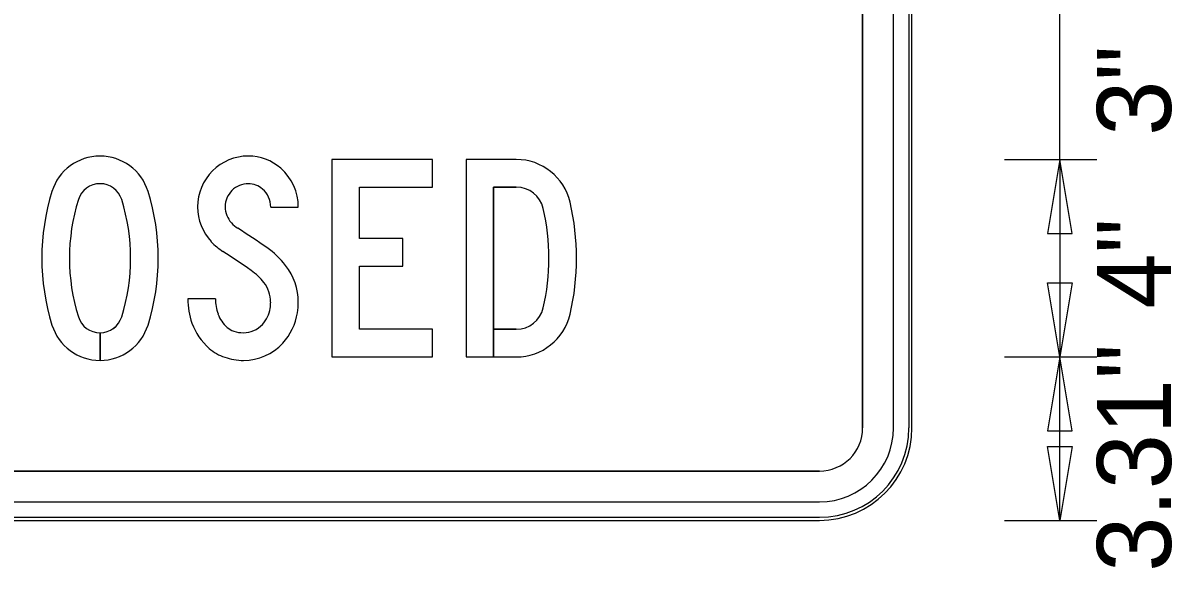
# Model space of a CAD drawing. Extents: x 1788.1 to 1851.2, y 237.2 to 283.4.
# Drawn here: x 1840.936 to 1843.265, y 275.952 to 277.056 of the extents above; entities that cross this region are included whole.
import ezdxf

# ---------------------------------------------------------------- set-up
doc = ezdxf.new("R2010")
doc.units = 0
for name, color, linetype in [('GSBWFILL', 7, 'Continuous'), ('GSCOLORFILL', 7, 'Continuous'), ('GSDIMS', 7, 'Continuous'), ('GSOUTLINE', 7, 'Continuous')]:
    doc.layers.add(name, color=color, linetype=linetype)

msp = doc.modelspace()

# ---------------------------------------------------------------- linework, layer by layer
at = {"layer": 'GSBWFILL'}
for p, q in [((1842.6379, 277.6605), (1842.6379, 276.2355)), ((1842.7004, 276.2355), (1842.7004, 277.6605)), ((1842.7379, 276.2355), (1842.7379, 277.6605)), ((1841.0919, 276.4282), (1841.0919, 276.3722)), ((1841.0919, 276.3722), (1841.0919, 276.4282)), ((1841.9358, 276.4352), (1841.8899, 276.4352)), ((1842.5504, 276.148), (1839.926, 276.148)), ((1839.926, 276.0855), (1842.5504, 276.0855)), ((1839.9254, 276.048), (1842.5504, 276.048))]:
    msp.add_line(p, q, dxfattribs=at)
msp.add_lwpolyline([(1841.6179, 276.4352), (1841.6179, 276.5632), (1841.7055, 276.5632), (1841.7055, 276.6192), (1841.6179, 276.6192), (1841.6179, 276.7232), (1841.7659, 276.7232), (1841.7659, 276.7792), (1841.5619, 276.7792), (1841.5619, 276.3792), (1841.7659, 276.3792), (1841.7659, 276.4352)], close=True, dxfattribs=at)
for points in [[(1841.9358, 276.7792), (1841.8339, 276.7792), (1841.8339, 276.3792), (1841.8899, 276.3792), (1841.8899, 276.7232), (1841.9358, 276.7232)], [(1841.4379, 276.6829), (1841.4939, 276.6829)], [(1841.3259, 276.4969), (1841.2699, 276.4969)], [(1841.8899, 276.4352), (1841.8899, 276.3792), (1841.9358, 276.3792)]]:
    msp.add_lwpolyline(points, dxfattribs=at)
for centre, radius, start, end in [((1841.0919, 276.6842), 0.102, 17.3283, 162.6717), ((1841.9358, 276.6672), 0.112, 13.109, 90), ((1841.0919, 276.6842), 0.046, 17.3283, 162.6717), ((1841.9358, 276.6672), 0.056, 13.109, 90), ((1841.4284, 276.5792), 0.4545, 162.6717, 197.3283), ((1841.4284, 276.5792), 0.3985, 162.6717, 197.3283), ((1840.7554, 276.5792), 0.3985, 342.6717, 17.3283), ((1840.7554, 276.5792), 0.4545, 342.6717, 17.3283), ((1841.5579, 276.5792), 0.444, 346.891, 13.109), ((1841.5579, 276.5792), 0.5, 346.891, 13.109), ((1841.9358, 276.4912), 0.056, 270, 346.891), ((1841.9358, 276.4912), 0.112, 270, 346.891), ((1841.0919, 276.4742), 0.102, 197.3283, 270), ((1841.0919, 276.4742), 0.046, 197.3283, 270), ((1841.0919, 276.4742), 0.046, 270.0249, 342.6717), ((1841.0919, 276.4742), 0.102, 270.0112, 342.6717), ((1842.5504, 276.2355), 0.15, 270, 0), ((1842.5504, 276.2355), 0.0875, 270, 0), ((1842.5504, 276.2355), 0.1875, 270, 0)]:
    msp.add_arc(centre, radius, start, end, dxfattribs=at)
for centre, major_axis, start_param, end_param in [((1841.3926, 276.6832), (0, 0.103), 6.283184, 7.853982), ((1841.3926, 276.6867), (0, 0.0995), 5.561989, 6.283185), ((1841.3893, 276.6829), (0, 0.1046), 4.712389, 5.561989), ((1841.3926, 276.6832), (0, 0.047), 6.283183, 7.853981), ((1841.3926, 276.6867), (0, 0.0435), 5.561989, 6.283185), ((1841.3893, 276.6829), (0, 0.0486), 4.712389, 5.561989), ((1841.3928, 276.6832), (0, 0.1032), 1.570796, 2.321595), ((1841.3928, 276.6832), (0, 0.0472), 1.570796, 2.321595), ((1841.4099, 276.699), (0, 0.0705), 2.321595, 2.56746), ((1840.093, 274.6631), (0, 2.3542), 5.679143, 5.709053), ((1841.4099, 276.699), (0, 0.1265), 2.321595, 2.56746), ((1840.093, 274.6631), (0, 2.2982), 5.679143, 5.709053), ((1841.3323, 276.4589), (0, 0.1722), 5.373599, 5.679143), ((1841.3323, 276.4589), (0, 0.1162), 5.373599, 5.679143), ((1841.372, 276.4899), (0, 0.1218), 4.712389, 5.373599), ((1841.372, 276.4899), (0, 0.0658), 4.712389, 5.373599), ((1841.4174, 276.4969), (0, 0.1475), 1.570808, 1.909921), ((1841.4174, 276.4969), (0, 0.0915), 1.570816, 1.909918), ((1841.3607, 276.4899), (0, 0.0772), 4.552917, 4.712389), ((1841.3607, 276.4899), (0, 0.1332), 4.552917, 4.712389), ((1841.3921, 276.488), (0, 0.0647), 1.909925, 2.431476), ((1841.3749, 276.4876), (0, 0.0628), 3.967076, 4.552917), ((1841.3749, 276.4876), (0, 0.1188), 3.967076, 4.552917), ((1841.3921, 276.488), (0, 0.1207), 1.909925, 2.431476), ((1841.3757, 276.4689), (0, 0.0396), 2.431476, 2.811358), ((1841.3827, 276.4804), (0, 0.0522), 3.141593, 3.967076), ((1841.3827, 276.4892), (0, 0.061), 2.811358, 3.141593), ((1841.3757, 276.4689), (0, 0.0956), 2.431476, 2.811358), ((1841.3827, 276.4804), (0, 0.1082), 3.141593, 3.967076), ((1841.3827, 276.4892), (0, 0.117), 2.811358, 3.141593)]:
    msp.add_ellipse(centre, major_axis=major_axis, ratio=0.999991, start_param=start_param, end_param=end_param, dxfattribs=at)
at = {"layer": 'GSCOLORFILL'}
for p, q in [((1842.6379, 277.6605), (1842.6379, 276.2355)), ((1842.7004, 276.2355), (1842.7004, 277.6605)), ((1842.7316, 277.6605), (1842.7316, 276.2355)), ((1842.7379, 276.2355), (1842.7379, 277.6605)), ((1842.7379, 276.2355), (1842.7379, 277.6605)), ((1841.0919, 276.4282), (1841.0919, 276.3722)), ((1841.0919, 276.3722), (1841.0919, 276.4282)), ((1841.9358, 276.4352), (1841.8899, 276.4352)), ((1842.5504, 276.148), (1839.926, 276.148)), ((1839.926, 276.0855), (1842.5504, 276.0855)), ((1839.9254, 276.048), (1842.5504, 276.048)), ((1842.5504, 276.0542), (1839.9255, 276.0542)), ((1839.9255, 276.048), (1842.5504, 276.048))]:
    msp.add_line(p, q, dxfattribs=at)
msp.add_lwpolyline([(1841.6179, 276.4352), (1841.6179, 276.5632), (1841.7055, 276.5632), (1841.7055, 276.6192), (1841.6179, 276.6192), (1841.6179, 276.7232), (1841.7659, 276.7232), (1841.7659, 276.7792), (1841.5619, 276.7792), (1841.5619, 276.3792), (1841.7659, 276.3792), (1841.7659, 276.4352)], close=True, dxfattribs=at)
for points in [[(1841.9358, 276.7792), (1841.8339, 276.7792), (1841.8339, 276.3792), (1841.8899, 276.3792), (1841.8899, 276.7232), (1841.9358, 276.7232)], [(1841.4379, 276.6829), (1841.4939, 276.6829)], [(1841.3259, 276.4969), (1841.2699, 276.4969)], [(1841.8899, 276.4352), (1841.8899, 276.3792), (1841.9358, 276.3792)]]:
    msp.add_lwpolyline(points, dxfattribs=at)
for centre, radius, start, end in [((1841.0919, 276.6842), 0.102, 17.3283, 162.6717), ((1841.9358, 276.6672), 0.112, 13.109, 90), ((1841.0919, 276.6842), 0.046, 17.3283, 162.6717), ((1841.9358, 276.6672), 0.056, 13.109, 90), ((1841.4284, 276.5792), 0.4545, 162.6717, 197.3283), ((1841.4284, 276.5792), 0.3985, 162.6717, 197.3283), ((1840.7554, 276.5792), 0.3985, 342.6717, 17.3283), ((1840.7554, 276.5792), 0.4545, 342.6717, 17.3283), ((1841.5579, 276.5792), 0.444, 346.891, 13.109), ((1841.5579, 276.5792), 0.5, 346.891, 13.109), ((1841.9358, 276.4912), 0.056, 270, 346.891), ((1841.9358, 276.4912), 0.112, 270, 346.891), ((1841.0919, 276.4742), 0.102, 197.3283, 270), ((1841.0919, 276.4742), 0.046, 197.3283, 270), ((1841.0919, 276.4742), 0.046, 270.0249, 342.6717), ((1841.0919, 276.4742), 0.102, 270.0112, 342.6717), ((1842.5504, 276.2355), 0.1875, 270, 0), ((1842.5504, 276.2355), 0.15, 270, 0), ((1842.5504, 276.2355), 0.0875, 270, 0), ((1842.5504, 276.2355), 0.1875, 270, 0), ((1842.5504, 276.2355), 0.1812, 270, 0)]:
    msp.add_arc(centre, radius, start, end, dxfattribs=at)
for centre, major_axis, start_param, end_param in [((1841.3926, 276.6832), (0, 0.103), 6.283184, 7.853982), ((1841.3926, 276.6867), (0, 0.0995), 5.561989, 6.283185), ((1841.3893, 276.6829), (0, 0.1046), 4.712389, 5.561989), ((1841.3926, 276.6832), (0, 0.047), 6.283183, 7.853981), ((1841.3926, 276.6867), (0, 0.0435), 5.561989, 6.283185), ((1841.3893, 276.6829), (0, 0.0486), 4.712389, 5.561989), ((1841.3928, 276.6832), (0, 0.1032), 1.570796, 2.321595), ((1841.3928, 276.6832), (0, 0.0472), 1.570796, 2.321595), ((1841.4099, 276.699), (0, 0.0705), 2.321595, 2.56746), ((1840.093, 274.6631), (0, 2.3542), 5.679143, 5.709053), ((1841.4099, 276.699), (0, 0.1265), 2.321595, 2.56746), ((1840.093, 274.6631), (0, 2.2982), 5.679143, 5.709053), ((1841.3323, 276.4589), (0, 0.1722), 5.373599, 5.679143), ((1841.3323, 276.4589), (0, 0.1162), 5.373599, 5.679143), ((1841.372, 276.4899), (0, 0.1218), 4.712389, 5.373599), ((1841.372, 276.4899), (0, 0.0658), 4.712389, 5.373599), ((1841.4174, 276.4969), (0, 0.1475), 1.570808, 1.909921), ((1841.4174, 276.4969), (0, 0.0915), 1.570816, 1.909918), ((1841.3607, 276.4899), (0, 0.0772), 4.552917, 4.712389), ((1841.3607, 276.4899), (0, 0.1332), 4.552917, 4.712389), ((1841.3921, 276.488), (0, 0.0647), 1.909925, 2.431476), ((1841.3749, 276.4876), (0, 0.0628), 3.967076, 4.552917), ((1841.3749, 276.4876), (0, 0.1188), 3.967076, 4.552917), ((1841.3921, 276.488), (0, 0.1207), 1.909925, 2.431476), ((1841.3757, 276.4689), (0, 0.0396), 2.431476, 2.811358), ((1841.3827, 276.4804), (0, 0.0522), 3.141593, 3.967076), ((1841.3827, 276.4892), (0, 0.061), 2.811358, 3.141593), ((1841.3757, 276.4689), (0, 0.0956), 2.431476, 2.811358), ((1841.3827, 276.4804), (0, 0.1082), 3.141593, 3.967076), ((1841.3827, 276.4892), (0, 0.117), 2.811358, 3.141593)]:
    msp.add_ellipse(centre, major_axis=major_axis, ratio=0.999991, start_param=start_param, end_param=end_param, dxfattribs=at)
at = {"layer": 'GSDIMS'}
for p, q in [((1843.0379, 276.7792), (1843.0379, 277.0792)), ((1842.9254, 276.7792), (1843.1129, 276.7792)), ((1842.9254, 276.7792), (1843.1129, 276.7792)), ((1843.0379, 276.7792), (1843.0379, 276.3792)), ((1842.9254, 276.3792), (1843.1129, 276.3792)), ((1842.9254, 276.3792), (1843.1129, 276.3792)), ((1843.0379, 276.048), (1843.0379, 276.3792)), ((1842.9254, 276.048), (1843.1129, 276.048)), ((1842.9254, 276.048), (1842.9254, 276.048))]:
    msp.add_line(p, q, dxfattribs=at)
for points in [[(1843.0379, 276.7792), (1843.0129, 276.6292), (1843.0629, 276.6292)], [(1843.0379, 276.3792), (1843.0129, 276.5292), (1843.0629, 276.5292)], [(1843.0379, 276.3792), (1843.0129, 276.2292), (1843.0629, 276.2292)], [(1843.0379, 276.048), (1843.0129, 276.198), (1843.0629, 276.198)]]:
    msp.add_lwpolyline(points, close=True, dxfattribs=at)
at = {"layer": 'GSOUTLINE'}
for p, q in [((1842.6379, 276.2355), (1842.6379, 277.6605)), ((1842.7004, 276.2355), (1842.7004, 277.6605)), ((1842.7379, 276.2355), (1842.7379, 277.6605)), ((1841.8899, 276.4352), (1841.9358, 276.4352)), ((1841.9358, 276.3792), (1841.9358, 276.3792)), ((1839.9254, 276.148), (1842.5504, 276.148)), ((1839.9254, 276.0855), (1842.5504, 276.0855)), ((1839.9254, 276.048), (1842.5504, 276.048))]:
    msp.add_line(p, q, dxfattribs=at)
msp.add_lwpolyline([(1841.6179, 276.4352), (1841.6179, 276.5632), (1841.7055, 276.5632), (1841.7055, 276.6192), (1841.6179, 276.6192), (1841.6179, 276.7232), (1841.7659, 276.7232), (1841.7659, 276.7792), (1841.5619, 276.7792), (1841.5619, 276.3792), (1841.7659, 276.3792), (1841.7659, 276.4352)], close=True, dxfattribs=at)
for points in [[(1841.9358, 276.7792), (1841.8339, 276.7792), (1841.8339, 276.3792), (1841.9358, 276.3792)], [(1841.9358, 276.7232), (1841.8899, 276.7232), (1841.8899, 276.4352)], [(1841.4379, 276.6829), (1841.4939, 276.6829)], [(1841.3259, 276.4969), (1841.2699, 276.4969)]]:
    msp.add_lwpolyline(points, dxfattribs=at)
for centre, radius, start, end in [((1841.0919, 276.6842), 0.102, 17.3283, 162.6717), ((1841.9358, 276.6672), 0.112, 13.109, 90), ((1841.0919, 276.6842), 0.046, 17.3283, 162.6717), ((1841.9358, 276.6672), 0.056, 13.109, 90), ((1841.4284, 276.5792), 0.4545, 162.6717, 197.3283), ((1841.4284, 276.5792), 0.3985, 162.6717, 197.3283), ((1840.7554, 276.5792), 0.3985, 342.6717, 17.3283), ((1840.7554, 276.5792), 0.4545, 342.6717, 17.3283), ((1841.5579, 276.5792), 0.444, 346.891, 13.109), ((1841.5579, 276.5792), 0.5, 346.891, 13.109), ((1841.9358, 276.4912), 0.056, 270, 346.891), ((1841.9358, 276.4912), 0.112, 270, 346.891), ((1841.0919, 276.4742), 0.102, 197.3283, 342.6717), ((1841.0919, 276.4742), 0.046, 197.3283, 342.6717), ((1842.5504, 276.2355), 0.15, 270, 0), ((1842.5504, 276.2355), 0.0875, 270, 0), ((1842.5504, 276.2355), 0.1875, 270, 0)]:
    msp.add_arc(centre, radius, start, end, dxfattribs=at)
for centre, major_axis, start_param, end_param in [((1841.3926, 276.6832), (0, 0.103), 6.283184, 7.853982), ((1841.3926, 276.6867), (0, 0.0995), 5.561989, 6.283185), ((1841.3893, 276.6829), (0, 0.1046), 4.712389, 5.561989), ((1841.3926, 276.6832), (0, 0.047), 6.283183, 7.853981), ((1841.3926, 276.6867), (0, 0.0435), 5.561989, 6.283185), ((1841.3893, 276.6829), (0, 0.0486), 4.712389, 5.561989), ((1841.3928, 276.6832), (0, 0.1032), 1.570796, 2.321595), ((1841.3928, 276.6832), (0, 0.0472), 1.570796, 2.321595), ((1841.4099, 276.699), (0, 0.0705), 2.321595, 2.56746), ((1840.093, 274.6631), (0, 2.3542), 5.679143, 5.709053), ((1841.4099, 276.699), (0, 0.1265), 2.321595, 2.56746), ((1840.093, 274.6631), (0, 2.2982), 5.679143, 5.709053), ((1841.3323, 276.4589), (0, 0.1722), 5.373599, 5.679143), ((1841.3323, 276.4589), (0, 0.1162), 5.373599, 5.679143), ((1841.372, 276.4899), (0, 0.1218), 4.712389, 5.373599), ((1841.372, 276.4899), (0, 0.0658), 4.712389, 5.373599), ((1841.4174, 276.4969), (0, 0.1475), 1.570808, 1.909921), ((1841.4174, 276.4969), (0, 0.0915), 1.570816, 1.909918), ((1841.3607, 276.4899), (0, 0.0772), 4.552917, 4.712389), ((1841.3607, 276.4899), (0, 0.1332), 4.552917, 4.712389), ((1841.3921, 276.488), (0, 0.0647), 1.909925, 2.431476), ((1841.3749, 276.4876), (0, 0.0628), 3.967076, 4.552917), ((1841.3749, 276.4876), (0, 0.1188), 3.967076, 4.552917), ((1841.3921, 276.488), (0, 0.1207), 1.909925, 2.431476), ((1841.3757, 276.4689), (0, 0.0396), 2.431476, 2.811358), ((1841.3827, 276.4804), (0, 0.0522), 3.141593, 3.967076), ((1841.3827, 276.4892), (0, 0.061), 2.811358, 3.141593), ((1841.3757, 276.4689), (0, 0.0956), 2.431476, 2.811358), ((1841.3827, 276.4804), (0, 0.1082), 3.141593, 3.967076), ((1841.3827, 276.4892), (0, 0.117), 2.811358, 3.141593)]:
    msp.add_ellipse(centre, major_axis=major_axis, ratio=0.999991, start_param=start_param, end_param=end_param, dxfattribs=at)

# ---------------------------------------------------------------- texts
at = {"layer": 'GSDIMS'}
for s, p in [('3"', (1843.2629, 276.8273)), ('4"', (1843.2629, 276.4773)), ('3.31"', (1843.2629, 275.944))]:
    msp.add_text(s, height=0.15, rotation=90, dxfattribs=at).set_placement(p)

doc.saveas('drawing.dxf')
